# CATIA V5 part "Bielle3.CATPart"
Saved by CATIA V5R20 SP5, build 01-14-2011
Part number: Bielle3
Bounding box of the stored display mesh (mm): x 20 to 40, y -161.991 to 9.991, z -311.965 to 9.965
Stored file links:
  E:\IAO_2010\iao\IAO_MMS_Groupe2\IAO_MMS_Groupe2\flafosse\Catia\IAO\Bielle3.CATPart
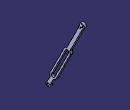
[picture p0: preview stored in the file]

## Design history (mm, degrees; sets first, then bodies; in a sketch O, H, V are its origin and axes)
Body1 (main body)
  Plane1: type Offset, RefPlane yz-plane, Offset 30
  Sketch1 on Plane1, origin (30, 0, 0), H (0, 1, 0), V (0, 0, 1)
    circle A1 centre (0, 0) radius 5
    radius A1 = 5
  Pad1: profile Sketch1, direction (1, 0, 0), length 10
  Point1 "E": stored without definition
  Point2 "E": stored without definition
  Sketch2 on Plane1, origin (30, 0, 0), H (0, 1, 0), V (0, 0, 1)
    arc A1 centre (0, 0) radius 10 from (3.7256, -9.2801) to (-9.673, -2.5364) ccw
    arc A2 centre (-152, -302) radius 10 from (-155.7256, -292.7199) to (-142.327, -299.4636) ccw
    point P1 (-152, -302)
    reference projected point E1 (-152, -302) from Point1
    circle A3 centre (-152, -302) radius 5
    construction line L1 (-152, -302) -> (0, 0)
    arc A4 centre (-129.5211, -257.338) radius 7.5 from (-136.2204, -253.9661) to (-122.8218, -260.7098) ccw
    point P2 (-129.5211, -257.338)
    point P3 (-132.8929, -264.0373)
    reference projected point E2 (-152, -302) from Point2
    arc A5 centre (-66.5801, -132.2842) radius 7.5 from (-59.8808, -135.6561) to (-73.2794, -128.9124) ccw
    point P4 (-66.5801, -132.2842)
    line L2 (-136.2204, -253.9661) -> (-73.2794, -128.9124)
    line L3 (-122.8218, -260.7098) -> (-59.8808, -135.6561)
    arc A6 centre (-66.5801, -132.2842) radius 15 from (-53.1815, -139.0279) to (-54.0406, -124.0525) ccw
    arc A7 centre (-129.5211, -257.338) radius 15 from (-142.9197, -250.5943) to (-142.0606, -265.5697) ccw
    line L4 (-79.9788, -125.5405) -> (-142.9197, -250.5943)
    line L5 (-53.1815, -139.0279) -> (-116.1225, -264.0816)
    line L6 (-67.4393, -117.3088) -> (-9.673, -2.5364)
    point P13 (-67.4393, -117.3088)
    line L7 (-54.0406, -124.0525) -> (3.7256, -9.2801)
    point P15 (-54.0406, -124.0525)
    arc A8 centre (-66.5801, -132.2842) radius 15 from (-67.4393, -117.3088) to (-79.9788, -125.5405) ccw
    line L8 (-142.0606, -265.5697) -> (-155.7256, -292.7199)
    point P17 (-142.0606, -265.5697)
    line L9 (-128.662, -272.3133) -> (-142.327, -299.4636)
    point P19 (-128.662, -272.3133)
    arc A9 centre (-129.5211, -257.338) radius 15 from (-128.662, -272.3133) to (-116.1225, -264.0816) ccw
    radius A1 = 10
    radius A2 = 10
    radius A3 = 5
    radius A4 = 7.5
    distance P2 E2 = 50
    radius A5 = 7.5
    distance P4 P2 = 140
    radius A6 = 15
    radius A7 = 15
    coincidence: P1 E1, P2 L1, A4 P3, P3 L1, P4 L1, P13 A6, P13 L2, P15 L3, A6 A8, P17 L2, P19 A7, P19 L3, A7 A9
    tangency: L2 A5, L3 A5, L3 A4, L2 A4, L4 A7, L5 A7, L4 A6, L5 A6, L6 A5, L7 A5, L8 A4, L9 A4
  Pad2: profile Sketch2, direction (-1, 0, 0), length 10
  Plane2: stored without definition
  Plane3: type Offset, RefPlane Plane2, Offset 25
  Line1 "Bielle 3": stored without definition
  Sketch3 on Plane3, origin (25, 0, 0), H (0, 1, 0), V (0, 0, 1)
    line L1 (-129.5211, -257.338) -> (-66.5801, -132.2842)
    point P1 (-129.5211, -257.338)
    point P2 (-66.5801, -132.2842)
    reference projected line E1 (0, 0) -> (-152, -302) from Line1
    reference projected arc E2 centre (-66.5801, -132.2842) radius 7.5 from (-59.8808, -135.6561) to (-73.2794, -128.9124) ccw from edge [start face of Pad2 | face of Pad2 from Sketch2.A5]
    reference projected arc E3 centre (-129.5211, -257.338) radius 7.5 from (-136.2204, -253.9661) to (-122.8218, -260.7098) ccw from edge [start face of Pad2 | face of Pad2 from Sketch2.A4]
    coincidence: L1 E1
    concentricity: E2 P2, P1 E3
  Sketch4 on start face of Pad2, origin (30, 0, 0), H (0, 1, 0), V (0, 0, 1)
    line L1 (-129.5211, -257.338) -> (-66.5801, -132.2842)
    point P1 (-129.5211, -257.338)
    point P2 (-66.5801, -132.2842)
    reference projected arc E1 centre (-66.5801, -132.2842) radius 7.5 from (-59.8808, -135.6561) to (-73.2794, -128.9124) ccw from edge [start face of Pad2 | face of Pad2 from Sketch2.A5]
    reference projected arc E2 centre (-129.5211, -257.338) radius 7.5 from (-136.2204, -253.9661) to (-122.8218, -260.7098) ccw from edge [start face of Pad2 | face of Pad2 from Sketch2.A4]
    concentricity: P2 E1, P1 E2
